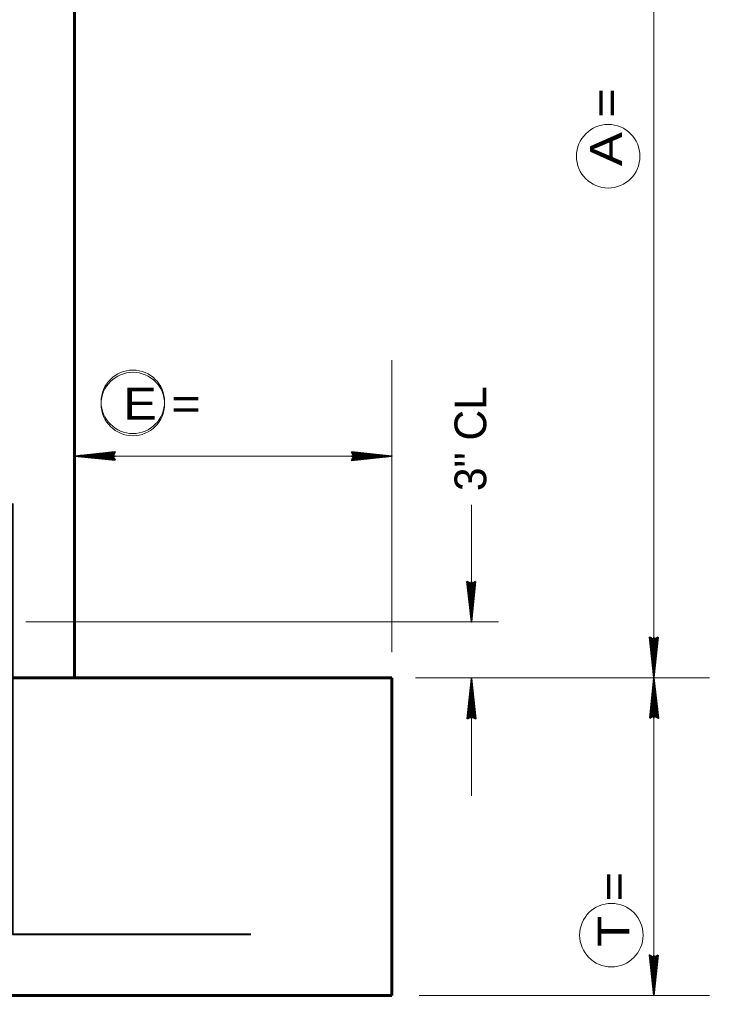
# Model space of a CAD drawing. Extents: x 6.34 to 9.53, y -1.46 to 0.53.
# Drawn here: x 7.9457 to 8.1267, y -0.8062 to -0.5501 of the extents above; entities that cross this region are included whole.
import ezdxf

# ---------------------------------------------------------------- set-up
doc = ezdxf.new("R2010")
doc.units = 0
doc.header["$LTSCALE"] = 0.0033
doc.layers.add('1', color=7, linetype='Continuous', lineweight=40)

msp = doc.modelspace()

# ---------------------------------------------------------------- linework, layer by layer
at = {"layer": '1', "lineweight": 13}
for p, q in [((8.112167, -0.805333), (8.112167, -0.389583)), ((8.043417, -0.716083), (8.043417, -0.6395)), ((7.961667, -0.664667), (8.043417, -0.664667)), ((8.06425, -0.69825), (8.06425, -0.677417)), ((7.947333, -0.708167), (8.071333, -0.708167)), ((8.049583, -0.722833), (8.12675, -0.722833)), ((8.06425, -0.75375), (8.06425, -0.732917)), ((7.996, -0.806167), (8.038, -0.806167)), ((8.050583, -0.806167), (8.12675, -0.806167))]:
    msp.add_line(p, q, dxfattribs=at)
at = {"layer": '1', "lineweight": 35}
for p, q in [((7.97075, -0.664667), (7.960167, -0.664667)), ((7.9705, -0.6655), (7.962667, -0.6645)), ((7.9705, -0.6655), (7.962667, -0.664667)), ((7.9705, -0.665667), (7.962667, -0.66475)), ((7.9705, -0.665667), (7.962667, -0.66475)), ((7.9705, -0.665583), (7.962667, -0.66475)), ((7.9705, -0.663583), (7.963167, -0.664417)), ((7.9705, -0.66375), (7.963167, -0.6645)), ((7.9705, -0.663833), (7.963167, -0.664667)), ((7.970583, -0.664), (7.96325, -0.66475)), ((8.032833, -0.664667), (8.043417, -0.664667)), ((8.033, -0.665333), (8.040333, -0.664583)), ((8.033083, -0.663667), (8.040917, -0.664583)), ((8.033083, -0.663667), (8.040917, -0.664583)), ((8.033083, -0.66375), (8.040917, -0.664583)), ((8.033083, -0.663833), (8.040917, -0.664667)), ((8.033083, -0.663833), (8.040917, -0.664833)), ((8.033083, -0.6655), (8.040417, -0.664667)), ((8.033083, -0.665583), (8.040417, -0.664833)), ((8.033083, -0.66575), (8.040417, -0.664917)), ((8.063167, -0.697833), (8.064, -0.705167)), ((8.063333, -0.697833), (8.064083, -0.705167)), ((8.063417, -0.697833), (8.06425, -0.705167)), ((8.063583, -0.69775), (8.064333, -0.705083)), ((8.065083, -0.697833), (8.064083, -0.705667)), ((8.06425, -0.697583), (8.06425, -0.708167)), ((8.065083, -0.697833), (8.06425, -0.705667)), ((8.06525, -0.697833), (8.064333, -0.705667)), ((8.06525, -0.697833), (8.064333, -0.705667)), ((8.065167, -0.697833), (8.064333, -0.705667)), ((8.111083, -0.712417), (8.111917, -0.71975)), ((8.11125, -0.712417), (8.112, -0.71975)), ((8.111333, -0.712417), (8.112167, -0.71975)), ((8.1115, -0.712333), (8.11225, -0.719667)), ((8.113, -0.712417), (8.112, -0.72025)), ((8.112167, -0.712167), (8.112167, -0.72275)), ((8.113, -0.712417), (8.112167, -0.72025)), ((8.113167, -0.712417), (8.11225, -0.72025)), ((8.113167, -0.712417), (8.11225, -0.72025)), ((8.113083, -0.712417), (8.11225, -0.72025)), ((8.06425, -0.733583), (8.06425, -0.723)), ((8.112167, -0.733417), (8.112167, -0.722833)), ((8.06325, -0.733333), (8.064167, -0.7255)), ((8.06325, -0.733333), (8.064167, -0.7255)), ((8.063333, -0.733333), (8.064167, -0.7255)), ((8.063417, -0.733333), (8.06425, -0.7255)), ((8.063417, -0.733333), (8.064417, -0.7255)), ((8.064917, -0.733417), (8.064167, -0.726083)), ((8.065083, -0.733333), (8.06425, -0.726)), ((8.065167, -0.733333), (8.064417, -0.726)), ((8.065333, -0.733333), (8.0645, -0.726)), ((8.111167, -0.733167), (8.112083, -0.725333)), ((8.111167, -0.733167), (8.112083, -0.725333)), ((8.11125, -0.733167), (8.112083, -0.725333)), ((8.111333, -0.733167), (8.112167, -0.725333)), ((8.111333, -0.733167), (8.112333, -0.725333)), ((8.112833, -0.73325), (8.112083, -0.725917)), ((8.113, -0.733167), (8.112167, -0.725833)), ((8.113083, -0.733167), (8.112333, -0.725833)), ((8.11325, -0.733167), (8.112417, -0.725833)), ((8.111083, -0.795833), (8.111917, -0.803167)), ((8.11125, -0.795833), (8.112, -0.803167)), ((8.111333, -0.795833), (8.112167, -0.803167)), ((8.1115, -0.79575), (8.11225, -0.803083)), ((8.113, -0.795833), (8.112, -0.803667)), ((8.112167, -0.795583), (8.112167, -0.806167)), ((8.113, -0.795833), (8.112167, -0.803667)), ((8.113167, -0.795833), (8.11225, -0.803667)), ((8.113167, -0.795833), (8.11225, -0.803667)), ((8.113083, -0.795833), (8.11225, -0.803667))]:
    msp.add_line(p, q, dxfattribs=at)
at = {"layer": '1', "lineweight": 60}
for p, q in [((8.043417, -0.722833), (8.043417, -0.806167)), ((8.043417, -0.806167), (7.710083, -0.806167))]:
    msp.add_line(p, q, dxfattribs=at)
for points in [[(7.710083, -0.722833), (7.793417, -0.722833), (7.793417, -0.3895), (7.960083, -0.3895), (7.960083, -0.722833), (8.043417, -0.722833)], [(7.793417, -0.722833), (7.855917, -0.722833), (7.855917, -0.702), (7.897583, -0.702), (7.897583, -0.722833), (7.960083, -0.722833)]]:
    msp.add_lwpolyline(points, dxfattribs=at)
at = {"layer": '1', "lineweight": 35}
for points in [[(7.97075, -0.66575), (7.960167, -0.664667), (7.97075, -0.6635), (7.970167, -0.664667)], [(7.97, -0.66475), (7.965333, -0.664833), (7.965333, -0.66475), (7.96625, -0.66475), (7.97, -0.664833), (7.967, -0.664917), (7.970167, -0.665), (7.967917, -0.665083), (7.970167, -0.665167), (7.966667, -0.664917), (7.962, -0.66475), (7.962917, -0.6645), (7.961667, -0.6645), (7.97, -0.6645), (7.967583, -0.664333), (7.970167, -0.664333), (7.964833, -0.66475), (7.970167, -0.664083)], [(8.032833, -0.663583), (8.043417, -0.664667), (8.032833, -0.665833), (8.033417, -0.664667)], [(8.033583, -0.664583), (8.03825, -0.6645), (8.03825, -0.664583), (8.037333, -0.664583), (8.033583, -0.6645), (8.036583, -0.664417), (8.033417, -0.664333), (8.035667, -0.66425), (8.033417, -0.664167), (8.036917, -0.664417), (8.041583, -0.664583), (8.040667, -0.664833), (8.041917, -0.664833), (8.033583, -0.664833), (8.036, -0.665), (8.033417, -0.665), (8.03875, -0.664583), (8.033417, -0.66525)], [(8.065333, -0.697583), (8.06425, -0.708167), (8.063083, -0.697583), (8.06425, -0.698167)], [(8.064333, -0.698333), (8.064417, -0.703), (8.064333, -0.703), (8.064333, -0.702083), (8.064417, -0.698333), (8.0645, -0.701333), (8.064583, -0.698167), (8.064667, -0.700417), (8.06475, -0.698167), (8.0645, -0.701667), (8.064333, -0.706333), (8.064083, -0.705417), (8.064083, -0.706667), (8.064083, -0.698333), (8.063917, -0.70075), (8.063917, -0.698167), (8.064333, -0.7035), (8.063667, -0.698167)], [(8.11325, -0.712167), (8.112167, -0.72275), (8.111, -0.712167), (8.112167, -0.71275)], [(8.11225, -0.712917), (8.112333, -0.717583), (8.11225, -0.717583), (8.11225, -0.716667), (8.112333, -0.712917), (8.112417, -0.715917), (8.1125, -0.71275), (8.112583, -0.715), (8.112667, -0.71275), (8.112417, -0.71625), (8.11225, -0.720917), (8.112, -0.72), (8.112, -0.72125), (8.112, -0.712917), (8.111833, -0.715333), (8.111833, -0.71275), (8.11225, -0.718083), (8.111583, -0.71275)], [(8.063167, -0.733583), (8.06425, -0.723), (8.065417, -0.733583), (8.06425, -0.733)], [(8.064167, -0.732833), (8.064083, -0.728167), (8.064167, -0.728167), (8.064167, -0.729083), (8.064083, -0.732833), (8.064, -0.729833), (8.063917, -0.733), (8.063833, -0.73075), (8.06375, -0.733), (8.064, -0.7295), (8.064167, -0.724833), (8.064417, -0.72575), (8.064417, -0.7245), (8.064417, -0.732833), (8.064583, -0.730417), (8.064583, -0.733), (8.064167, -0.727667), (8.064833, -0.733)], [(8.111083, -0.733417), (8.112167, -0.722833), (8.113333, -0.733417), (8.112167, -0.732833)], [(8.112083, -0.732667), (8.112, -0.728), (8.112083, -0.728), (8.112083, -0.728917), (8.112, -0.732667), (8.111917, -0.729667), (8.111833, -0.732833), (8.11175, -0.730583), (8.111667, -0.732833), (8.111917, -0.729333), (8.112083, -0.724667), (8.112333, -0.725583), (8.112333, -0.724333), (8.112333, -0.732667), (8.1125, -0.73025), (8.1125, -0.732833), (8.112083, -0.7275), (8.11275, -0.732833)], [(8.11325, -0.795583), (8.112167, -0.806167), (8.111, -0.795583), (8.112167, -0.796167)], [(8.11225, -0.796333), (8.112333, -0.801), (8.11225, -0.801), (8.11225, -0.800083), (8.112333, -0.796333), (8.112417, -0.799333), (8.1125, -0.796167), (8.112583, -0.798417), (8.112667, -0.796167), (8.112417, -0.799667), (8.11225, -0.804333), (8.112, -0.803417), (8.112, -0.804667), (8.112, -0.796333), (8.111833, -0.79875), (8.111833, -0.796167), (8.11225, -0.8015), (8.111583, -0.796167)]]:
    msp.add_lwpolyline(points, close=True, dxfattribs=at)
for points in [[(7.97, -0.66475), (7.970417, -0.6655), (7.970167, -0.66525), (7.97, -0.664917), (7.96975, -0.665), (7.969917, -0.665333), (7.970083, -0.664583), (7.97025, -0.664083), (7.9705, -0.663667)], [(8.033583, -0.664583), (8.033167, -0.663833), (8.033417, -0.664083), (8.033583, -0.664417), (8.033833, -0.664333), (8.033667, -0.664), (8.0335, -0.66475), (8.033333, -0.66525), (8.033083, -0.665667)], [(8.064333, -0.698333), (8.065083, -0.697917), (8.064833, -0.698167), (8.0645, -0.698333), (8.064583, -0.698583), (8.064917, -0.698417), (8.064167, -0.69825), (8.063667, -0.698083), (8.06325, -0.697833)], [(8.11225, -0.712917), (8.113, -0.7125), (8.11275, -0.71275), (8.112417, -0.712917), (8.1125, -0.713167), (8.112833, -0.713), (8.112083, -0.712833), (8.111583, -0.712667), (8.111167, -0.712417)], [(8.064167, -0.732833), (8.063417, -0.73325), (8.063667, -0.733), (8.064, -0.732833), (8.063917, -0.732583), (8.063583, -0.73275), (8.064333, -0.732917), (8.064833, -0.733083), (8.06525, -0.733333)], [(8.112083, -0.732667), (8.111333, -0.733083), (8.111583, -0.732833), (8.111917, -0.732667), (8.111833, -0.732417), (8.1115, -0.732583), (8.11225, -0.73275), (8.11275, -0.732917), (8.113167, -0.733167)], [(8.11225, -0.796333), (8.113, -0.795917), (8.11275, -0.796167), (8.112417, -0.796333), (8.1125, -0.796583), (8.112833, -0.796417), (8.112083, -0.79625), (8.111583, -0.796083), (8.111167, -0.795833)]]:
    msp.add_lwpolyline(points, dxfattribs=at)
at = {"layer": '1'}
msp.add_lwpolyline([(7.943833, -0.677083), (7.943833, -0.790083), (8.006333, -0.790083)], dxfattribs=at)
at = {"layer": '1', "lineweight": 13}
for centre in [(8.100167, -0.586), (7.975417, -0.650417), (7.975417, -0.651), (8.101, -0.790333)]:
    msp.add_circle(centre, 0.008333, dxfattribs=at)

# ---------------------------------------------------------------- texts
at = {"layer": '1', "width": 1.2}
for s, p in [('A =      ', (8.10375, -0.588583)), ('T =      ', (8.10575, -0.793417))]:
    msp.add_text(s, height=0.008334, rotation=90, dxfattribs=at).set_placement(p)
msp.add_text('E =      ', height=0.008334, dxfattribs=at).set_placement((7.972833, -0.655083))
at = {"layer": '1'}
msp.add_text('3" CL', height=0.008334, rotation=90, dxfattribs=at).set_placement((8.068167, -0.673833))

doc.saveas('drawing.dxf')
